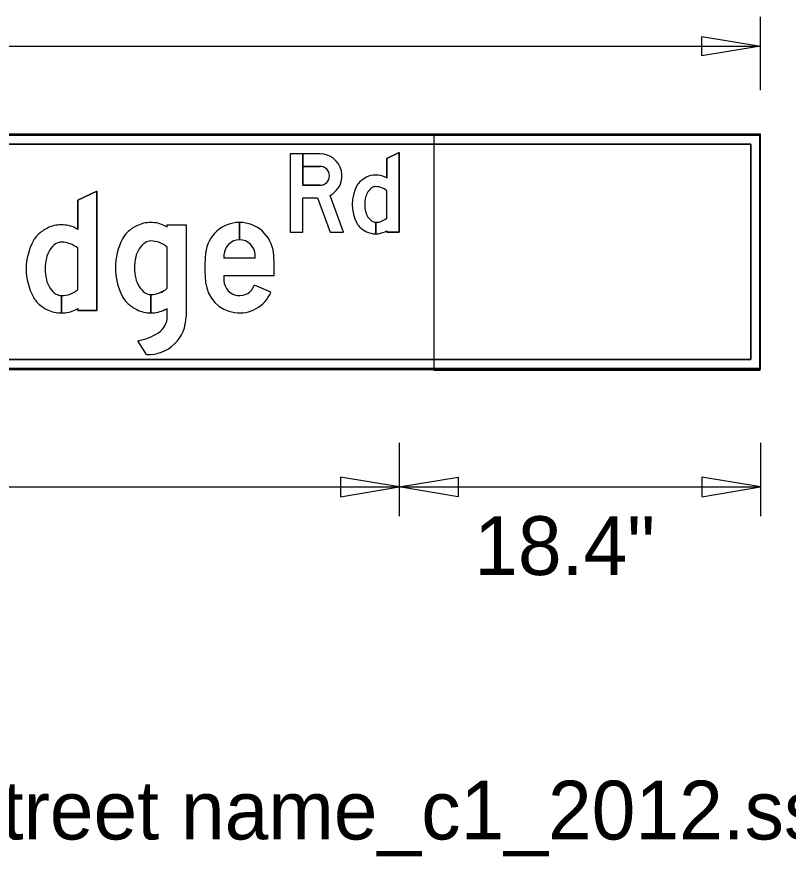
# Model space of a CAD drawing. Extents: x 1708.4 to 1771.6, y 238.3 to 283.4.
# Drawn here: x 1729.072 to 1733.009, y 273.743 to 278.033 of the extents above; entities that cross this region are included whole.
import ezdxf

# ---------------------------------------------------------------- set-up
doc = ezdxf.new("R2010")
doc.units = 0
for name, color, linetype in [('Level 11', 7, 'Continuous'), ('Level 2', 7, 'Continuous'), ('Level 3', 7, 'Continuous'), ('Level 4', 7, 'Continuous'), ('Level 5', 7, 'Continuous')]:
    doc.layers.add(name, color=color, linetype=linetype)

msp = doc.modelspace()

# ---------------------------------------------------------------- linework, layer by layer
at = {"layer": 'Level 11'}
msp.add_lwpolyline([(1731.2022, 277.428), (1732.8625, 277.428), (1732.8625, 276.228), (1731.2022, 276.228)], close=True, dxfattribs=at)
at = {"layer": 'Level 2'}
for p, q in [((1732.8675, 277.433), (1724.4675, 277.433)), ((1732.8675, 277.433), (1724.4675, 277.433)), ((1732.8675, 277.433), (1724.4675, 277.433)), ((1724.4725, 277.428), (1732.8625, 277.428)), ((1732.8625, 277.428), (1732.8625, 276.238)), ((1732.8675, 276.233), (1732.8675, 277.433)), ((1732.8675, 276.233), (1732.8675, 277.433)), ((1732.8675, 276.233), (1732.8675, 277.433)), ((1724.5175, 277.383), (1732.8175, 277.383)), ((1732.8175, 277.383), (1732.8175, 276.283)), ((1730.2085, 276.8945), (1730.2085, 276.983)), ((1730.2085, 276.983), (1730.2085, 276.8945)), ((1729.8395, 276.647), (1729.8395, 276.857)), ((1730.2888, 276.8), (1730.1282, 276.8)), ((1730.128, 276.7115), (1730.3844, 276.7115)), ((1730.3688, 276.6272), (1730.2839, 276.6632)), ((1729.7555, 276.6155), (1729.7555, 276.521)), ((1729.7555, 276.521), (1729.7555, 276.6155)), ((1729.8395, 276.503), (1729.8395, 276.5446)), ((1729.7341, 276.3081), (1729.6885, 276.3786)), ((1732.8175, 276.283), (1724.4675, 276.283)), ((1732.8625, 276.238), (1724.4675, 276.238)), ((1724.4675, 276.233), (1732.8675, 276.233)), ((1724.4675, 276.233), (1732.8675, 276.233)), ((1724.4675, 276.233), (1732.8675, 276.233))]:
    msp.add_line(p, q, dxfattribs=at)
for points in [[(1730.9595, 277.2095), (1730.9595, 277.309), (1731.0235, 277.34), (1731.0235, 276.933), (1730.9595, 276.933), (1730.9595, 276.9405)], [(1730.6194, 277.173), (1730.5315, 277.173), (1730.5315, 277.333), (1730.4675, 277.333), (1730.4675, 276.933), (1730.5315, 276.933), (1730.5315, 277.109), (1730.6066, 277.109), (1730.6713, 276.933), (1730.7395, 276.933), (1730.6703, 277.1212)], [(1730.5315, 277.333), (1730.5315, 277.269), (1730.6194, 277.269)], [(1730.6194, 277.333), (1730.5315, 277.333)], [(1729.3835, 276.9478), (1729.3835, 277.097), (1729.4795, 277.1435), (1729.4795, 276.533), (1729.3835, 276.533), (1729.3835, 276.5442)], [(1730.9595, 277.005), (1730.9595, 277.145)], [(1729.8395, 276.9594), (1729.8395, 276.971), (1729.9355, 276.971), (1729.9355, 276.503)], [(1730.9035, 276.984), (1730.9035, 276.925)], [(1730.9035, 276.925), (1730.9035, 276.984)], [(1729.3835, 276.641), (1729.3835, 276.851)], [(1729.2995, 276.6095), (1729.2995, 276.521)], [(1729.2995, 276.521), (1729.2995, 276.6095)]]:
    msp.add_lwpolyline(points, dxfattribs=at)
for centre, radius, start, end in [((1730.9133, 277.0964), 0.1309, 116.0163, 133.5224), ((1730.9035, 277.1164), 0.1086, 90, 116.0163), ((1730.9035, 277.1164), 0.1086, 63.9837, 90), ((1730.8937, 277.0964), 0.1309, 59.8311, 63.9837), ((1730.9861, 277.075), 0.2026, 151.6141, 208.3859), ((1730.8782, 277.1333), 0.08, 133.5224, 151.6141), ((1730.9035, 277.1305), 0.0355, 90, 123.9444), ((1730.9035, 277.0808), 0.0852, 48.8879, 90), ((1730.9498, 277.0865), 0.1009, 148.3925, 165.6998), ((1730.9213, 277.104), 0.0675, 123.9444, 148.3925), ((1730.9949, 277.075), 0.1474, 165.6998, 180), ((1730.9949, 277.075), 0.1474, 180, 194.3002), ((1730.9498, 277.0635), 0.1009, 194.3002, 211.6075), ((1730.9213, 277.046), 0.0675, 211.6075, 236.0556), ((1730.9035, 277.0692), 0.0852, 270.0067, 311.1121), ((1729.3142, 276.7781), 0.1963, 116.0163, 133.5224), ((1729.2995, 276.8081), 0.1629, 90, 116.0163), ((1729.2995, 276.8081), 0.1629, 63.9837, 90), ((1729.2848, 276.7781), 0.1963, 59.8311, 63.9837), ((1729.7725, 276.7884), 0.1986, 116.4894, 133.8571), ((1729.7555, 276.8224), 0.1606, 90, 116.4894), ((1729.7555, 276.8224), 0.1606, 63.5106, 90), ((1729.7385, 276.7884), 0.1986, 59.4445, 63.5106), ((1730.8782, 277.0167), 0.08, 208.3859, 226.4776), ((1730.9133, 277.0536), 0.1309, 226.4776, 243.9837), ((1730.9035, 277.0195), 0.0355, 236.0556, 270), ((1729.2616, 276.8334), 0.12, 133.5224, 151.6141), ((1729.718, 276.8451), 0.12, 133.8571, 152.8113), ((1730.9035, 277.0336), 0.1086, 243.9837, 270), ((1730.9035, 277.0336), 0.1086, 270.0053, 296.0163), ((1730.8937, 277.0536), 0.1309, 296.0163, 300.1689), ((1729.4234, 276.746), 0.3039, 151.6141, 208.3859), ((1729.3263, 276.7895), 0.1012, 123.9444, 148.3925), ((1729.2995, 276.8293), 0.0532, 90, 123.9444), ((1729.2995, 276.7547), 0.1278, 48.8879, 90), ((1729.8992, 276.752), 0.3237, 152.8113, 207.1887), ((1729.7823, 276.7955), 0.1012, 123.9444, 148.3925), ((1729.7555, 276.8353), 0.0532, 90, 123.9444), ((1729.7555, 276.7608), 0.1277, 48.8879, 90), ((1729.3689, 276.7632), 0.1513, 148.3925, 165.6998), ((1729.8249, 276.7692), 0.1513, 148.3925, 165.6998), ((1729.4366, 276.746), 0.2211, 165.6998, 180), ((1729.8926, 276.752), 0.2211, 165.6998, 180), ((1729.4366, 276.746), 0.2211, 180, 194.3002), ((1729.8926, 276.752), 0.2211, 180, 194.3002), ((1729.8249, 276.7348), 0.1513, 194.3002, 211.6075), ((1729.3689, 276.7288), 0.1513, 194.3002, 211.6075), ((1729.7823, 276.7085), 0.1012, 211.6075, 236.0556), ((1729.3263, 276.7025), 0.1012, 211.6075, 236.0556), ((1729.2995, 276.6627), 0.0532, 236.0556, 270), ((1729.2995, 276.7373), 0.1278, 270.0067, 311.1121), ((1729.7555, 276.6687), 0.0532, 236.0556, 270), ((1729.7555, 276.7432), 0.1277, 270.0135, 311.1121), ((1729.2616, 276.6586), 0.12, 208.3859, 226.4776), ((1729.3142, 276.7139), 0.1963, 226.4776, 243.9837), ((1729.718, 276.6589), 0.12, 207.1887, 226.1429), ((1729.7725, 276.7156), 0.1986, 226.1429, 243.5106), ((1729.2995, 276.6839), 0.1629, 243.9837, 270), ((1729.2995, 276.6839), 0.1629, 270.0053, 296.0163), ((1729.2848, 276.7139), 0.1963, 296.0163, 300.1689), ((1729.7555, 276.6816), 0.1606, 243.5106, 270), ((1729.7555, 276.6816), 0.1606, 270.0107, 296.4894), ((1729.7385, 276.7156), 0.1986, 296.4894, 300.5555), ((1729.7405, 276.503), 0.195, 268.1286, 0), ((1729.7405, 276.503), 0.099, 302.9057, 0), ((1729.6405, 276.6575), 0.283, 279.7616, 302.9057)]:
    msp.add_arc(centre, radius, start, end, dxfattribs=at)
for centre, major_axis, ratio, start_param, end_param in [((1730.6194, 277.221), (0, 0.112), 0.999993, 3.613317, 6.283185), ((1730.6194, 277.221), (0, 0.048), 0.999993, 3.141593, 6.283185), ((1730.2085, 276.8089), (0, 0.1741), 0.999992, 0, 1.470576), ((1730.2085, 276.8089), (0, 0.1741), 0.999992, 4.81261, 6.283013), ((1730.2085, 276.8148), (0, 0.0797), 0.999992, 0, 1.530173), ((1730.2085, 276.8148), (0, 0.0797), 0.999992, 4.753012, 6.282809), ((1730.7739, 276.752), (0, 0.7424), 0.999992, 1.470576, 1.570796), ((1729.6431, 276.752), (0, 0.7424), 0.999992, 4.712389, 4.81261), ((1731.7529, 276.752), (0, 1.6255), 0.999992, 1.530173, 1.541262), ((1728.6641, 276.752), (0, 1.6255), 0.999992, 4.741924, 4.753012), ((1730.7739, 276.752), (0, 0.7424), 0.999992, 1.570796, 1.671017), ((1729.6431, 276.752), (0, 0.7424), 0.999992, 4.657806, 4.712389), ((1731.7529, 276.752), (0, 1.6255), 0.999992, 1.595715, 1.61142), ((1730.2085, 276.6951), (0, 0.1741), 0.999992, 1.671017, 4.311605), ((1730.2085, 276.6892), (0, 0.0797), 0.999992, 1.61142, 4.380076)]:
    msp.add_ellipse(centre, major_axis=major_axis, ratio=ratio, start_param=start_param, end_param=end_param, dxfattribs=at)
at = {"layer": 'Level 3'}
for p, q in [((1732.8675, 277.433), (1724.4675, 277.433)), ((1732.8675, 277.433), (1724.4675, 277.433)), ((1732.8675, 276.233), (1732.8675, 277.433)), ((1732.8675, 276.233), (1732.8675, 277.433)), ((1732.8175, 277.383), (1724.5175, 277.383)), ((1732.8175, 276.283), (1732.8175, 277.383)), ((1729.8395, 276.647), (1729.8395, 276.857)), ((1730.2888, 276.8), (1730.1282, 276.8)), ((1730.128, 276.7115), (1730.3844, 276.7115)), ((1730.3688, 276.6272), (1730.2839, 276.6632)), ((1730.2839, 276.6632), (1730.2839, 276.6632)), ((1729.8395, 276.503), (1729.8395, 276.5446)), ((1729.7341, 276.3081), (1729.6885, 276.3786)), ((1724.5175, 276.283), (1732.8175, 276.283)), ((1724.4675, 276.233), (1732.8675, 276.233)), ((1724.4675, 276.233), (1732.8675, 276.233))]:
    msp.add_line(p, q, dxfattribs=at)
for points in [[(1730.9595, 276.9405), (1730.9595, 276.933), (1731.0235, 276.933), (1731.0235, 277.34), (1730.9595, 277.309), (1730.9595, 277.2095)], [(1730.6194, 277.333), (1730.4675, 277.333), (1730.4675, 276.933), (1730.5315, 276.933), (1730.5315, 277.109), (1730.6066, 277.109), (1730.6713, 276.933), (1730.7395, 276.933), (1730.6703, 277.1212)], [(1730.6194, 277.269), (1730.5315, 277.269), (1730.5315, 277.173), (1730.6194, 277.173)], [(1729.3835, 276.5442), (1729.3835, 276.533), (1729.4795, 276.533), (1729.4795, 277.1435), (1729.3835, 277.097), (1729.3835, 276.9478)], [(1730.9595, 277.005), (1730.9595, 277.145)], [(1729.8395, 276.9594), (1729.8395, 276.971), (1729.9355, 276.971), (1729.9355, 276.503)], [(1729.3835, 276.641), (1729.3835, 276.851)]]:
    msp.add_lwpolyline(points, dxfattribs=at)
for centre, radius, start, end in [((1730.9133, 277.0964), 0.1309, 116.0163, 133.5224), ((1730.9035, 277.1164), 0.1086, 90, 116.0163), ((1730.9035, 277.1164), 0.1086, 63.9837, 90), ((1730.8937, 277.0964), 0.1309, 59.8311, 63.9837), ((1730.9861, 277.075), 0.2026, 151.6141, 208.3859), ((1730.8782, 277.1333), 0.08, 133.5224, 151.6141), ((1730.9035, 277.1305), 0.0355, 90, 123.9444), ((1730.9035, 277.0808), 0.0852, 48.8879, 90), ((1730.9498, 277.0865), 0.1009, 148.3925, 165.6998), ((1730.9213, 277.104), 0.0675, 123.9444, 148.3925), ((1730.9949, 277.075), 0.1474, 165.6998, 180), ((1730.9949, 277.075), 0.1474, 180, 194.3002), ((1730.9498, 277.0635), 0.1009, 194.3002, 211.6075), ((1730.9213, 277.046), 0.0675, 211.6075, 236.0556), ((1730.9035, 277.0692), 0.0852, 270, 311.1121), ((1729.3142, 276.7781), 0.1963, 116.0163, 133.5224), ((1729.2995, 276.8081), 0.1629, 90, 116.0163), ((1729.2995, 276.8081), 0.1629, 63.9837, 90), ((1729.2848, 276.7781), 0.1963, 59.8311, 63.9837), ((1729.7725, 276.7884), 0.1986, 116.4894, 133.8571), ((1729.7555, 276.8224), 0.1606, 90, 116.4894), ((1729.7555, 276.8224), 0.1606, 63.5106, 90), ((1729.7385, 276.7884), 0.1986, 59.4445, 63.5106), ((1730.8782, 277.0167), 0.08, 208.3859, 226.4776), ((1730.9133, 277.0536), 0.1309, 226.4776, 243.9837), ((1730.9035, 277.0195), 0.0355, 236.0556, 270), ((1729.2616, 276.8334), 0.12, 133.5224, 151.6141), ((1729.718, 276.8451), 0.12, 133.8571, 152.8113), ((1730.9035, 277.0336), 0.1086, 243.9837, 270), ((1730.9035, 277.0336), 0.1086, 270.0053, 296.0163), ((1730.9035, 277.0336), 0.1086, 270, 270.0053), ((1730.8937, 277.0536), 0.1309, 296.0163, 300.1689), ((1729.4234, 276.746), 0.3039, 151.6141, 208.3859), ((1729.3263, 276.7895), 0.1012, 123.9444, 148.3925), ((1729.2995, 276.8293), 0.0532, 90, 123.9444), ((1729.2995, 276.7547), 0.1278, 48.8879, 90), ((1729.8992, 276.752), 0.3237, 152.8113, 207.1887), ((1729.7823, 276.7955), 0.1012, 123.9444, 148.3925), ((1729.7555, 276.8353), 0.0532, 90, 123.9444), ((1729.7555, 276.7608), 0.1277, 48.8879, 90), ((1729.3689, 276.7632), 0.1513, 148.3925, 165.6998), ((1729.8249, 276.7692), 0.1513, 148.3925, 165.6998), ((1729.4366, 276.746), 0.2211, 165.6998, 180), ((1729.8926, 276.752), 0.2211, 165.6998, 180), ((1729.4366, 276.746), 0.2211, 180, 194.3002), ((1729.8926, 276.752), 0.2211, 180, 194.3002), ((1729.8249, 276.7348), 0.1513, 194.3002, 211.6075), ((1729.3689, 276.7288), 0.1513, 194.3002, 211.6075), ((1729.7823, 276.7085), 0.1012, 211.6075, 236.0556), ((1729.3263, 276.7025), 0.1012, 211.6075, 236.0556), ((1729.2995, 276.6627), 0.0532, 236.0556, 270), ((1729.2995, 276.7373), 0.1278, 270, 311.1121), ((1729.7555, 276.6687), 0.0532, 236.0556, 270), ((1729.7555, 276.7432), 0.1278, 270, 311.1121), ((1729.2616, 276.6586), 0.12, 208.3859, 226.4776), ((1729.3142, 276.7139), 0.1963, 226.4776, 243.9837), ((1729.718, 276.6589), 0.12, 207.1887, 226.1429), ((1729.7725, 276.7156), 0.1986, 226.1429, 243.5106), ((1729.2995, 276.6839), 0.1629, 243.9837, 270), ((1729.2995, 276.6839), 0.1629, 270.0053, 296.0163), ((1729.2848, 276.7139), 0.1963, 296.0163, 300.1689), ((1729.7555, 276.6816), 0.1606, 243.5106, 270), ((1729.7555, 276.6816), 0.1606, 270, 296.4894), ((1729.7385, 276.7156), 0.1986, 296.4894, 300.5555), ((1729.2995, 276.6839), 0.1629, 270, 270.0053), ((1729.7405, 276.503), 0.195, 268.1286, 0), ((1729.7405, 276.503), 0.099, 302.9057, 0), ((1729.6405, 276.6575), 0.283, 279.7616, 302.9057)]:
    msp.add_arc(centre, radius, start, end, dxfattribs=at)
for centre, major_axis, ratio, start_param, end_param in [((1730.6194, 277.221), (0, 0.112), 0.999993, 3.613317, 6.283185), ((1730.6194, 277.221), (0, 0.048), 0.999993, 3.141593, 6.283185), ((1730.2085, 276.8089), (0, 0.1741), 0.999992, 4.81261, 7.753761), ((1730.2085, 276.8148), (0, 0.0797), 0.999992, 4.753012, 7.813358), ((1730.7739, 276.752), (0, 0.7424), 0.999992, 1.470576, 1.570796), ((1729.6431, 276.752), (0, 0.7424), 0.999992, 4.712389, 4.81261), ((1731.7529, 276.752), (0, 1.6255), 0.999992, 1.530173, 1.541262), ((1728.6641, 276.752), (0, 1.6255), 0.999992, 4.741924, 4.753012), ((1730.7739, 276.752), (0, 0.7424), 0.999992, 1.570796, 1.671017), ((1729.6431, 276.752), (0, 0.7424), 0.999992, 4.657806, 4.712389), ((1731.7529, 276.752), (0, 1.6255), 0.999992, 1.595715, 1.61142), ((1730.2085, 276.6951), (0, 0.1741), 0.999992, 1.671017, 4.311605), ((1730.2085, 276.6892), (0, 0.0797), 0.999992, 1.61142, 4.380076)]:
    msp.add_ellipse(centre, major_axis=major_axis, ratio=ratio, start_param=start_param, end_param=end_param, dxfattribs=at)
at = {"layer": 'Level 4'}
for p, q in [((1732.8675, 277.433), (1724.4675, 277.433)), ((1732.8675, 277.433), (1724.4675, 277.433)), ((1732.8675, 276.233), (1732.8675, 277.433)), ((1732.8675, 276.233), (1732.8675, 277.433)), ((1724.5175, 277.383), (1732.8175, 277.383)), ((1732.8175, 277.383), (1732.8175, 276.283)), ((1730.2085, 276.8945), (1730.2085, 276.983)), ((1730.2085, 276.983), (1730.2085, 276.8945)), ((1729.8395, 276.647), (1729.8395, 276.857)), ((1730.2888, 276.8), (1730.1282, 276.8)), ((1730.128, 276.7115), (1730.3844, 276.7115)), ((1730.3688, 276.6272), (1730.2839, 276.6632)), ((1729.7555, 276.6155), (1729.7555, 276.521)), ((1729.7555, 276.521), (1729.7555, 276.6155)), ((1729.8395, 276.503), (1729.8395, 276.5446)), ((1729.7341, 276.3081), (1729.6885, 276.3786)), ((1732.8175, 276.283), (1724.4675, 276.283)), ((1724.4675, 276.233), (1732.8675, 276.233)), ((1724.4675, 276.233), (1732.8675, 276.233))]:
    msp.add_line(p, q, dxfattribs=at)
for points in [[(1730.9595, 277.2095), (1730.9595, 277.309), (1731.0235, 277.34), (1731.0235, 276.933), (1730.9595, 276.933), (1730.9595, 276.9405)], [(1730.6194, 277.173), (1730.5315, 277.173), (1730.5315, 277.333), (1730.4675, 277.333), (1730.4675, 276.933), (1730.5315, 276.933), (1730.5315, 277.109), (1730.6066, 277.109), (1730.6713, 276.933), (1730.7395, 276.933), (1730.6703, 277.1212)], [(1730.5315, 277.333), (1730.5315, 277.269), (1730.6194, 277.269)], [(1730.6194, 277.333), (1730.5315, 277.333)], [(1729.3835, 276.9478), (1729.3835, 277.097), (1729.4795, 277.1435), (1729.4795, 276.533), (1729.3835, 276.533), (1729.3835, 276.5442)], [(1730.9595, 277.005), (1730.9595, 277.145)], [(1729.8395, 276.9594), (1729.8395, 276.971), (1729.9355, 276.971), (1729.9355, 276.503)], [(1730.9035, 276.984), (1730.9035, 276.925)], [(1730.9035, 276.925), (1730.9035, 276.984)], [(1729.3835, 276.641), (1729.3835, 276.851)], [(1729.2995, 276.6095), (1729.2995, 276.521)], [(1729.2995, 276.521), (1729.2995, 276.6095)]]:
    msp.add_lwpolyline(points, dxfattribs=at)
for centre, radius, start, end in [((1730.9133, 277.0964), 0.1309, 116.0163, 133.5224), ((1730.9035, 277.1164), 0.1086, 90, 116.0163), ((1730.9035, 277.1164), 0.1086, 63.9837, 90), ((1730.8937, 277.0964), 0.1309, 59.8311, 63.9837), ((1730.9861, 277.075), 0.2026, 151.6141, 208.3859), ((1730.8782, 277.1333), 0.08, 133.5224, 151.6141), ((1730.9035, 277.1305), 0.0355, 90, 123.9444), ((1730.9035, 277.0808), 0.0852, 48.8879, 90), ((1730.9498, 277.0865), 0.1009, 148.3925, 165.6998), ((1730.9213, 277.104), 0.0675, 123.9444, 148.3925), ((1730.9949, 277.075), 0.1474, 165.6998, 180), ((1730.9949, 277.075), 0.1474, 180, 194.3002), ((1730.9498, 277.0635), 0.1009, 194.3002, 211.6075), ((1730.9213, 277.046), 0.0675, 211.6075, 236.0556), ((1730.9035, 277.0692), 0.0852, 270.0067, 311.1121), ((1729.3142, 276.7781), 0.1963, 116.0163, 133.5224), ((1729.2995, 276.8081), 0.1629, 90, 116.0163), ((1729.2995, 276.8081), 0.1629, 63.9837, 90), ((1729.2848, 276.7781), 0.1963, 59.8311, 63.9837), ((1729.7725, 276.7884), 0.1986, 116.4894, 133.8571), ((1729.7555, 276.8224), 0.1606, 90, 116.4894), ((1729.7555, 276.8224), 0.1606, 63.5106, 90), ((1729.7385, 276.7884), 0.1986, 59.4445, 63.5106), ((1730.8782, 277.0167), 0.08, 208.3859, 226.4776), ((1730.9133, 277.0536), 0.1309, 226.4776, 243.9837), ((1730.9035, 277.0195), 0.0355, 236.0556, 270), ((1729.2616, 276.8334), 0.12, 133.5224, 151.6141), ((1729.718, 276.8451), 0.12, 133.8571, 152.8113), ((1730.9035, 277.0336), 0.1086, 243.9837, 270), ((1730.9035, 277.0336), 0.1086, 270.0053, 296.0163), ((1730.8937, 277.0536), 0.1309, 296.0163, 300.1689), ((1729.4234, 276.746), 0.3039, 151.6141, 208.3859), ((1729.3263, 276.7895), 0.1012, 123.9444, 148.3925), ((1729.2995, 276.8293), 0.0532, 90, 123.9444), ((1729.2995, 276.7547), 0.1278, 48.8879, 90), ((1729.8992, 276.752), 0.3237, 152.8113, 207.1887), ((1729.7823, 276.7955), 0.1012, 123.9444, 148.3925), ((1729.7555, 276.8353), 0.0532, 90, 123.9444), ((1729.7555, 276.7608), 0.1277, 48.8879, 90), ((1729.3689, 276.7632), 0.1513, 148.3925, 165.6998), ((1729.8249, 276.7692), 0.1513, 148.3925, 165.6998), ((1729.4366, 276.746), 0.2211, 165.6998, 180), ((1729.8926, 276.752), 0.2211, 165.6998, 180), ((1729.4366, 276.746), 0.2211, 180, 194.3002), ((1729.8926, 276.752), 0.2211, 180, 194.3002), ((1729.8249, 276.7348), 0.1513, 194.3002, 211.6075), ((1729.3689, 276.7288), 0.1513, 194.3002, 211.6075), ((1729.7823, 276.7085), 0.1012, 211.6075, 236.0556), ((1729.3263, 276.7025), 0.1012, 211.6075, 236.0556), ((1729.2995, 276.6627), 0.0532, 236.0556, 270), ((1729.2995, 276.7373), 0.1278, 270.0067, 311.1121), ((1729.7555, 276.6687), 0.0532, 236.0556, 270), ((1729.7555, 276.7432), 0.1277, 270.0135, 311.1121), ((1729.2616, 276.6586), 0.12, 208.3859, 226.4776), ((1729.3142, 276.7139), 0.1963, 226.4776, 243.9837), ((1729.718, 276.6589), 0.12, 207.1887, 226.1429), ((1729.7725, 276.7156), 0.1986, 226.1429, 243.5106), ((1729.2995, 276.6839), 0.1629, 243.9837, 270), ((1729.2995, 276.6839), 0.1629, 270.0053, 296.0163), ((1729.2848, 276.7139), 0.1963, 296.0163, 300.1689), ((1729.7555, 276.6816), 0.1606, 243.5106, 270), ((1729.7555, 276.6816), 0.1606, 270.0107, 296.4894), ((1729.7385, 276.7156), 0.1986, 296.4894, 300.5555), ((1729.7405, 276.503), 0.195, 268.1286, 0), ((1729.7405, 276.503), 0.099, 302.9057, 0), ((1729.6405, 276.6575), 0.283, 279.7616, 302.9057)]:
    msp.add_arc(centre, radius, start, end, dxfattribs=at)
for centre, major_axis, ratio, start_param, end_param in [((1730.6194, 277.221), (0, 0.112), 0.999993, 3.613317, 6.283185), ((1730.6194, 277.221), (0, 0.048), 0.999993, 3.141593, 6.283185), ((1730.2085, 276.8089), (0, 0.1741), 0.999992, 0, 1.470576), ((1730.2085, 276.8089), (0, 0.1741), 0.999992, 4.81261, 6.283013), ((1730.2085, 276.8148), (0, 0.0797), 0.999992, 0, 1.530173), ((1730.2085, 276.8148), (0, 0.0797), 0.999992, 4.753012, 6.282809), ((1730.7739, 276.752), (0, 0.7424), 0.999992, 1.470576, 1.570796), ((1729.6431, 276.752), (0, 0.7424), 0.999992, 4.712389, 4.81261), ((1731.7529, 276.752), (0, 1.6255), 0.999992, 1.530173, 1.541262), ((1728.6641, 276.752), (0, 1.6255), 0.999992, 4.741924, 4.753012), ((1730.7739, 276.752), (0, 0.7424), 0.999992, 1.570796, 1.671017), ((1729.6431, 276.752), (0, 0.7424), 0.999992, 4.657806, 4.712389), ((1731.7529, 276.752), (0, 1.6255), 0.999992, 1.595715, 1.61142), ((1730.2085, 276.6951), (0, 0.1741), 0.999992, 1.671017, 4.311605), ((1730.2085, 276.6892), (0, 0.0797), 0.999992, 1.61142, 4.380076)]:
    msp.add_ellipse(centre, major_axis=major_axis, ratio=ratio, start_param=start_param, end_param=end_param, dxfattribs=at)
at = {"layer": 'Level 5'}
for p, q in [((1732.8675, 277.658), (1732.8675, 278.033)), ((1724.4675, 277.883), (1732.8675, 277.883)), ((1732.8675, 277.658), (1732.8675, 277.658)), ((1731.0235, 275.858), (1731.0235, 275.483)), ((1731.0235, 275.858), (1731.0235, 275.483)), ((1732.8675, 275.858), (1732.8675, 275.483)), ((1732.8675, 275.858), (1732.8675, 275.483)), ((1724.6675, 275.633), (1731.0235, 275.633)), ((1731.0235, 275.633), (1732.8675, 275.633))]:
    msp.add_line(p, q, dxfattribs=at)
for points in [[(1732.8675, 277.883), (1732.5675, 277.833), (1732.5675, 277.933)], [(1731.0235, 275.633), (1730.7235, 275.683), (1730.7235, 275.583)], [(1731.0235, 275.633), (1731.3235, 275.683), (1731.3235, 275.583)], [(1732.8675, 275.633), (1732.5675, 275.683), (1732.5675, 275.583)]]:
    msp.add_lwpolyline(points, close=True, dxfattribs=at)

# ---------------------------------------------------------------- texts
for s, p in [('18.4"', (1731.4062, 275.183)), ('Panel Style: guide_con_street name_c1_2012.ssi', (1724.4675, 273.833))]:
    msp.add_text(s, height=0.3, dxfattribs=at).set_placement(p)

doc.saveas('drawing.dxf')
